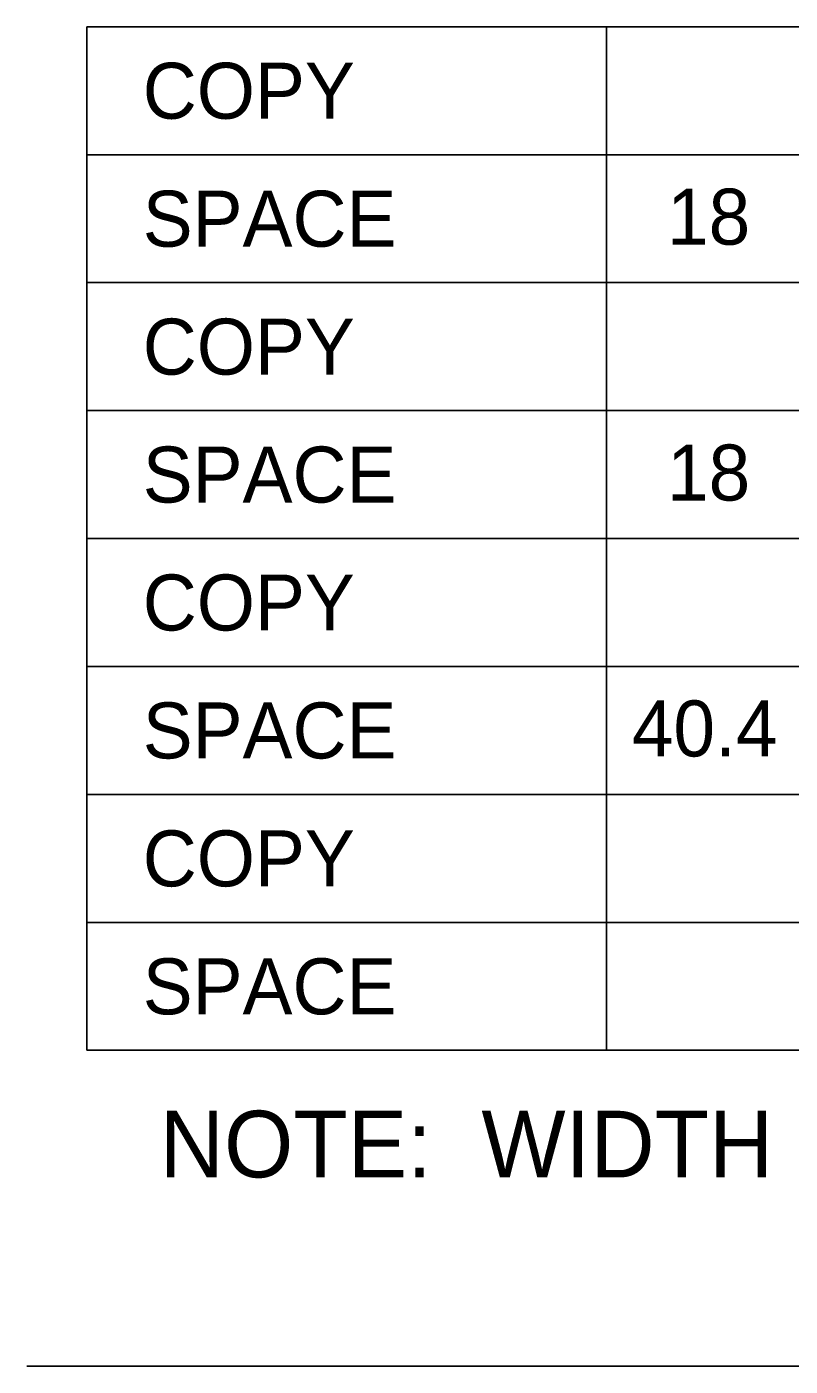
# Model space of a CAD drawing. Extents: x 10268312 to 10268472, y 2142583 to 2142688.
# Drawn here: x 10268317.73 to 10268327.28, y 2142640.28 to 2142657.03 of the extents above; entities that cross this region are included whole.
import ezdxf

# ---------------------------------------------------------------- set-up
doc = ezdxf.new("R2010")
doc.units = 0
for name, color, linetype in [('SheetBorder_dp', 7, 'Continuous'), ('SumBoxLines_dp', 7, 'Continuous'), ('SumBoxLinesMin_dp', 7, 'Continuous'), ('TextLabel', 7, 'Continuous'), ('TextMisc', 7, 'Continuous'), ('TextNotes', 7, 'Continuous')]:
    doc.layers.add(name, color=color, linetype=linetype)

msp = doc.modelspace()

# ---------------------------------------------------------------- linework, layer by layer
at = {"layer": 'SheetBorder_dp'}
msp.add_line((10268317.73, 2142640.282), (10268471.73, 2142640.282), dxfattribs=at)
at = {"layer": 'SumBoxLines_dp'}
for p, q in [((10268318.48, 2142657.032), (10268393.98, 2142657.032)), ((10268318.48, 2142657.032), (10268318.48, 2142644.232)), ((10268324.98, 2142657.032), (10268324.98, 2142644.232)), ((10268318.48, 2142653.832), (10268393.98, 2142653.832)), ((10268318.48, 2142650.632), (10268393.98, 2142650.632)), ((10268318.48, 2142647.432), (10268393.98, 2142647.432)), ((10268318.48, 2142644.232), (10268393.98, 2142644.232))]:
    msp.add_line(p, q, dxfattribs=at)
at = {"layer": 'SumBoxLinesMin_dp'}
for p, q in [((10268318.48, 2142655.432), (10268393.98, 2142655.432)), ((10268318.48, 2142652.232), (10268393.98, 2142652.232)), ((10268318.48, 2142649.032), (10268393.98, 2142649.032)), ((10268318.48, 2142645.832), (10268393.98, 2142645.832))]:
    msp.add_line(p, q, dxfattribs=at)

# ---------------------------------------------------------------- texts
at = {"layer": 'TextLabel'}
for s, p in [('18', (10268325.737, 2142654.307)), ('18', (10268325.737, 2142651.107)), ('40.4', (10268325.297, 2142647.907))]:
    msp.add_text(s, height=0.7, dxfattribs=at).set_placement(p)
at = {"layer": 'TextMisc'}
for s, p in [('COPY', (10268319.18, 2142655.882)), ('SPACE', (10268319.18, 2142654.282)), ('COPY', (10268319.18, 2142652.682)), ('SPACE', (10268319.18, 2142651.082)), ('COPY', (10268319.18, 2142649.482)), ('SPACE', (10268319.18, 2142647.882)), ('COPY', (10268319.18, 2142646.282)), ('SPACE', (10268319.18, 2142644.682))]:
    msp.add_text(s, height=0.7, dxfattribs=at).set_placement(p)
at = {"layer": 'TextNotes'}
msp.add_text('NOTE:  WIDTH - HORIZONTAL SPACING DIMENSIONS ARE IN INCHES.', height=0.83333, dxfattribs=at).set_placement((10268319.392, 2142642.643))

doc.saveas('drawing.dxf')
